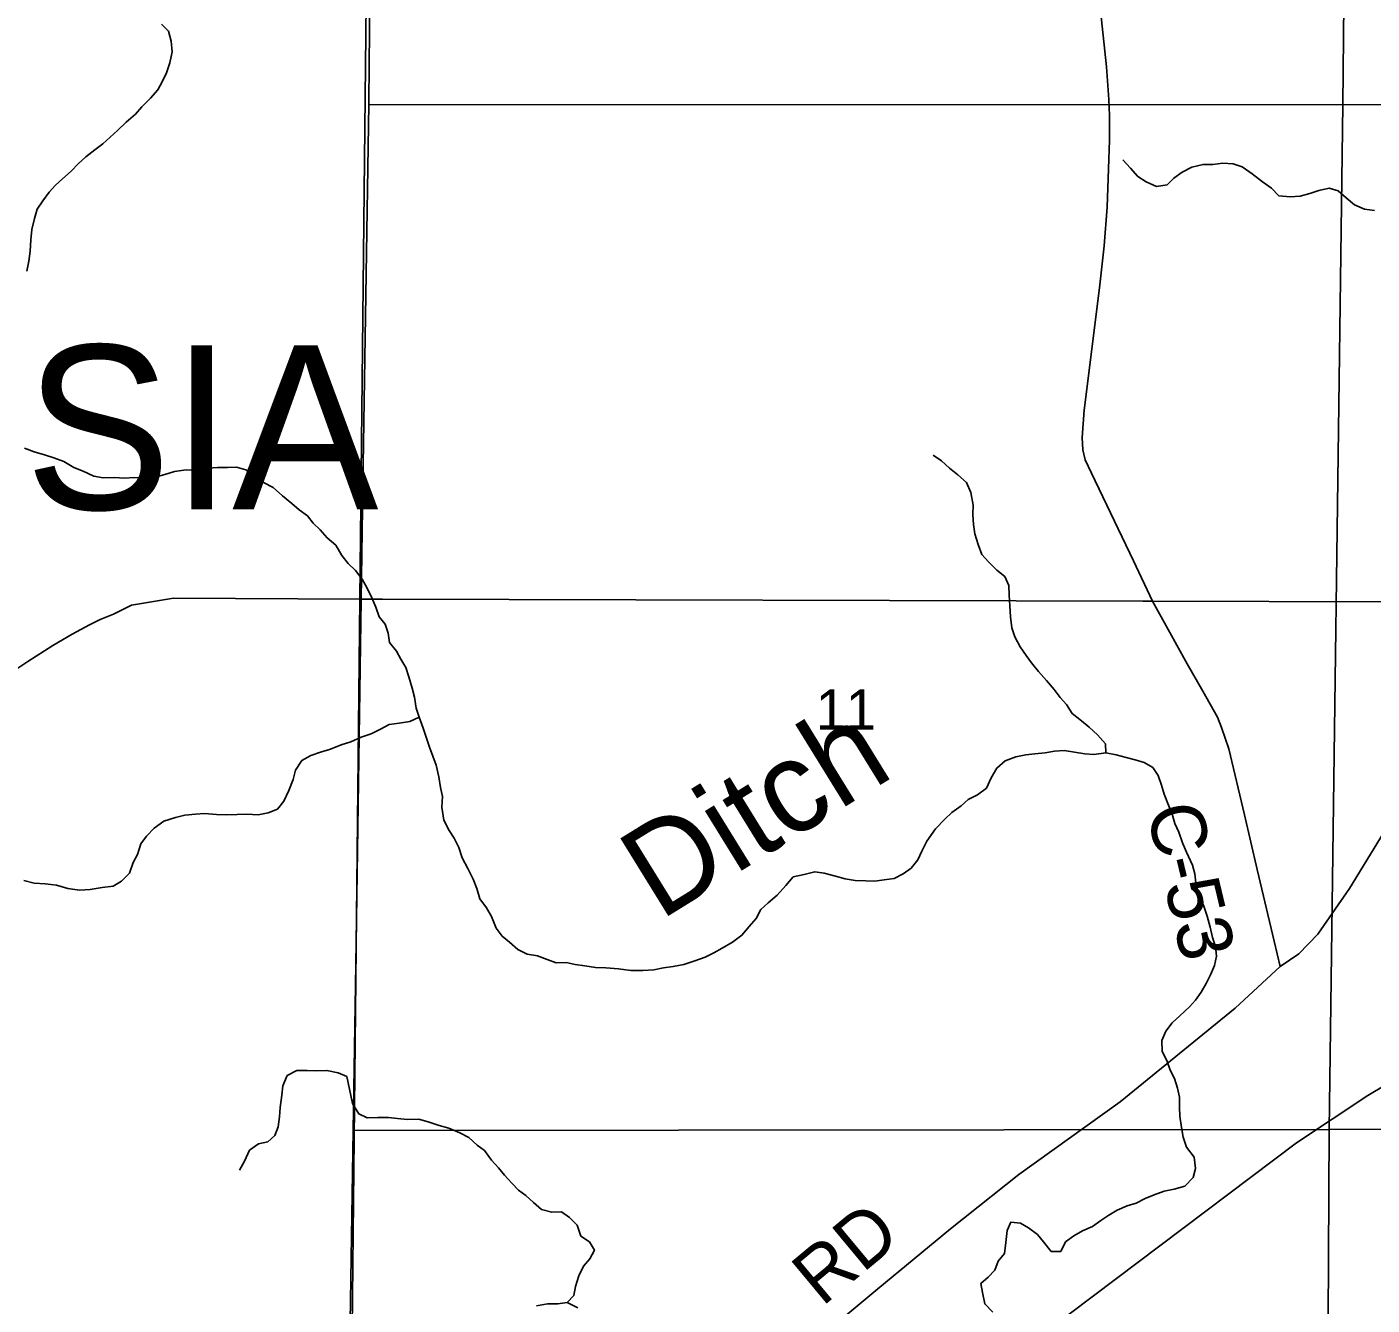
# Model space of a CAD drawing. Extents: x 1857828 to 2277390, y 930619 to 1324581.
# Drawn here: x 2058380 to 2065754, y 1203389 to 1210395 of the extents above; entities that cross this region are included whole.
import ezdxf

# ---------------------------------------------------------------- set-up
doc = ezdxf.new("R2010")
doc.units = 0
for name, color, linetype in [('GM_X_County_Road', 7, 'Continuous'), ('GM_X_County_Road_Text', 7, 'Continuous'), ('GM_X_Minor_River', 7, 'Continuous'), ('GM_X_Minor_River_Text', 7, 'Continuous'), ('GM_X_Section', 7, 'Continuous'), ('GM_X_Section_Text', 7, 'Continuous'), ('GM_X_Township', 7, 'Continuous'), ('GM_X_Township_Road', 7, 'Continuous'), ('GM_X_Township_Text', 7, 'Continuous'), ('GM_X_US_Route', 7, 'Continuous')]:
    doc.layers.add(name, color=color, linetype=linetype)

msp = doc.modelspace()

# ---------------------------------------------------------------- linework, layer by layer
at = {"layer": 'GM_X_County_Road'}
for points in [[(2064549.9, 1207247.2), (2064446.4, 1207468.3), (2064216.2, 1207950), (2064181.6, 1208021.9), (2064167.5, 1208077.3), (2064163.8, 1208144.2), (2064175.6, 1208295), (2064259.9, 1208964.2), (2064285.9, 1209194.8), (2064301.5, 1209407.9), (2064309.7, 1209616.9), (2064314.4, 1209774), (2064314.6, 1209909.9), (2064310.8, 1209997.3), (2064297.5, 1210177.2), (2064265.8, 1210485)], [(2060140.1, 1201171.9), (2060205.6, 1201229.4), (2061510.6, 1202210.1), (2062685.1, 1203178.1), (2063045, 1203479.1), (2063443.3, 1203807.8), (2063817.2, 1204104.5), (2064372.5, 1204503.7), (2065003.2, 1205016.3), (2065250.1, 1205245.6), (2065353, 1205315.3), (2065456.4, 1205422.5), (2065629.4, 1205673.4), (2066300.4, 1206769.3), (2066531.4, 1207209.6)], [(2065250.1, 1205245.6), (2065217.4, 1205384), (2065124.4, 1205777.5), (2065054, 1206075.6), (2064968.1, 1206439.1), (2064929.4, 1206555.6), (2064907.5, 1206612.1), (2064826.3, 1206754.6), (2064741.2, 1206904), (2064549.9, 1207247.2)]]:
    msp.add_lwpolyline(points, dxfattribs=at)
at = {"layer": 'GM_X_Minor_River'}
for points in [[(2058378.6, 1209057.1), (2058390.8, 1209111.1), (2058397, 1209165.2), (2058401.3, 1209227.3), (2058407.5, 1209285.4), (2058421.8, 1209345.5), (2058436, 1209395.6), (2058466.2, 1209441.5), (2058502.4, 1209489.5), (2058536.6, 1209527.4), (2058574.7, 1209563.3), (2058622.9, 1209605.2), (2058661.1, 1209645.1), (2058703.2, 1209683), (2058751.4, 1209720.8), (2058795.5, 1209754.7), (2058835.7, 1209790.6), (2058875.8, 1209826.5), (2058924, 1209872.4), (2058974.2, 1209916.3), (2059010.4, 1209956.2), (2059056.6, 1210004.1), (2059096.8, 1210050), (2059123, 1210098), (2059145.2, 1210144), (2059163.4, 1210198), (2059175.6, 1210258.1), (2059169.9, 1210316.3), (2059156.1, 1210372.4), (2059118.3, 1210410.7)], [(2065766.6, 1209388.5), (2065712.6, 1209396.5), (2065658.5, 1209420.5), (2065612.4, 1209458.5), (2065568.3, 1209496.5), (2065518.3, 1209510.5), (2065462.3, 1209498.4), (2065412.3, 1209482.3), (2065360.3, 1209468.1), (2065304.3, 1209464.1), (2065242.3, 1209470), (2065202.2, 1209512), (2065154.1, 1209546), (2065096, 1209590.1), (2065041.9, 1209628.1), (2064991.9, 1209644), (2064935.9, 1209648), (2064881.9, 1209641.9), (2064827.9, 1209641.8), (2064765.9, 1209625.7), (2064712, 1209599.6), (2064668, 1209565.4), (2064630.1, 1209529.3), (2064572.1, 1209521.2), (2064516.1, 1209545.2), (2064470, 1209575.2), (2064429.9, 1209621.2), (2064387.7, 1209667.2)], [(2060026, 1207594.5), (2059987.9, 1207638.6), (2059949.8, 1207674.6), (2059917.7, 1207714.6), (2059871.6, 1207748.7), (2059831.5, 1207782.7), (2059781.4, 1207824.7), (2059729.3, 1207870.7), (2059677.2, 1207898.7), (2059629.2, 1207936.8), (2059579.1, 1207966.7), (2059529, 1207982.7), (2059479, 1207980.6), (2059425, 1207980.6), (2059373, 1207976.5), (2059319, 1207966.4), (2059253, 1207968.3), (2059189, 1207958.2), (2059135.1, 1207942.1), (2059075.1, 1207925.9), (2059017.1, 1207923.9), (2058967.1, 1207925.8), (2058915.1, 1207921.7), (2058859.1, 1207925.6), (2058797.1, 1207923.6), (2058747.1, 1207933.5), (2058689, 1207959.5), (2058636.9, 1207979.5), (2058582.8, 1208013.4), (2058526.8, 1208033.4), (2058476.7, 1208049.4), (2058418.7, 1208065.3), (2058366.7, 1208085.3)], [(2064295.3, 1206415.9), (2064291.8, 1206465.9), (2064248, 1206514.2), (2064202.2, 1206556.5), (2064160.3, 1206590.8), (2064110.5, 1206631.1), (2064078.7, 1206681.3), (2064044.9, 1206719.6), (2064011.1, 1206763.8), (2063969.3, 1206812.1), (2063925.5, 1206862.4), (2063887.7, 1206908.7), (2063857.8, 1206949), (2063824, 1206997.2), (2063796.3, 1207051.5), (2063778.5, 1207101.7), (2063772.7, 1207161.8), (2063769, 1207222), (2063765.2, 1207280.1), (2063763.4, 1207334.2), (2063741.6, 1207382.5), (2063697.8, 1207416.7), (2063652, 1207463.1), (2063614.2, 1207503.3), (2063594.4, 1207557.5), (2063576.6, 1207615.8), (2063568.8, 1207667.9), (2063565.1, 1207722), (2063567.3, 1207774.1), (2063553.6, 1207842.3), (2063529.8, 1207898.6), (2063484, 1207940.9), (2063438.1, 1207977.2), (2063394.3, 1208017.5), (2063348.4, 1208047.8)], [(2063855.2, 1206405.2), (2063801.2, 1206395.1), (2063743.3, 1206373), (2063697.4, 1206332.8), (2063665.5, 1206278.7), (2063639.6, 1206222.5), (2063591.7, 1206186.4), (2063539.8, 1206160.2), (2063501.8, 1206126.1), (2063449.9, 1206089.9), (2063412, 1206051.8), (2063360.1, 1205999.6), (2063312.3, 1205931.4), (2063286.4, 1205877.2), (2063264.5, 1205829.1), (2063226.6, 1205785), (2063182.7, 1205752.8), (2063134.7, 1205726.7), (2063078.7, 1205720.6), (2063028.7, 1205712.5), (2062978.7, 1205714.4), (2062920.7, 1205716.4), (2062864.7, 1205726.3), (2062812.6, 1205740.3), (2062750.6, 1205756.2), (2062698.6, 1205764.2), (2062640.6, 1205750.1), (2062580.6, 1205735.9), (2062540.7, 1205689.8), (2062492.8, 1205635.6), (2062442.9, 1205593.4), (2062403, 1205557.3), (2062377.1, 1205509.1), (2062339.2, 1205465), (2062299.3, 1205416.8), (2062247.4, 1205378.7), (2062191.5, 1205346.5), (2062145.5, 1205320.4), (2062097.6, 1205296.3), (2062041.6, 1205276.1), (2061981.7, 1205256), (2061921.7, 1205245.9), (2061869.7, 1205237.8), (2061815.7, 1205227.7), (2061755.7, 1205223.6), (2061689.7, 1205223.5), (2061623.7, 1205231.5), (2061553.6, 1205237.4), (2061497.6, 1205239.3), (2061437.6, 1205249.2), (2061385.6, 1205255.2), (2061335.6, 1205267.1), (2061281.5, 1205265.1), (2061231.5, 1205283), (2061179.5, 1205303), (2061121.4, 1205312.9), (2061071.4, 1205338.9), (2061025.3, 1205378.9), (2060985.2, 1205411), (2060953.1, 1205455), (2060926.9, 1205519.1), (2060898.8, 1205567.2), (2060862.7, 1205615.2), (2060846.6, 1205673.3), (2060826.4, 1205723.4), (2060796.3, 1205781.5), (2060766.2, 1205841.6), (2060748, 1205897.7), (2060721.9, 1205947.8), (2060693.8, 1205989.8), (2060665.7, 1206047.9), (2060653.5, 1206118.1), (2060657.4, 1206176.2), (2060647.2, 1206226.3), (2060637.1, 1206284.4), (2060623, 1206348.6), (2060604.8, 1206398.6), (2060586.7, 1206446.7), (2060570.6, 1206496.8), (2060552.5, 1206550.9), (2060530.3, 1206611), (2060514.2, 1206661.1), (2060504.1, 1206721.2), (2060492, 1206771.3), (2060473.8, 1206833.4), (2060457.7, 1206883.5), (2060429.6, 1206929.6), (2060405.5, 1206973.7), (2060367.4, 1207021.7), (2060359.3, 1207071.8), (2060343.1, 1207121.9), (2060311, 1207161.9), (2060292.9, 1207214.1), (2060270.8, 1207266.1), (2060244.7, 1207318.2), (2060218.5, 1207368.3), (2060180.4, 1207416.3), (2060140.3, 1207454.4), (2060106.2, 1207498.4), (2060074.1, 1207554.5), (2060026, 1207594.5)], [(2060530.3, 1206611), (2060478.4, 1206588.9), (2060420.4, 1206578.8), (2060366.4, 1206570.7), (2060318.5, 1206546.6), (2060266.5, 1206520.4), (2060212.6, 1206502.3), (2060154.6, 1206476.2), (2060102.6, 1206460.1), (2060044.7, 1206435.9), (2059988.7, 1206419.8), (2059936.8, 1206401.7), (2059886.8, 1206373.6), (2059852.9, 1206321.4), (2059839.1, 1206269.3), (2059815.2, 1206209.1), (2059787.3, 1206150.9), (2059753.4, 1206106.8), (2059701.5, 1206086.7), (2059647.5, 1206076.6), (2059585.5, 1206080.5), (2059531.5, 1206078.4), (2059475.5, 1206076.3), (2059419.4, 1206078.3), (2059353.4, 1206084.2), (2059303.4, 1206080.1), (2059245.4, 1206074), (2059193.5, 1206061.9), (2059129.5, 1206041.8), (2059077.6, 1206003.6), (2059035.7, 1205959.4), (2059003.8, 1205917.3), (2058985.9, 1205859.1), (2058962, 1205815), (2058942.1, 1205756.8), (2058898.2, 1205712.7), (2058852.3, 1205684.6), (2058792.3, 1205678.5), (2058726.3, 1205666.3), (2058668.3, 1205664.3), (2058604.3, 1205672.2), (2058542.2, 1205690.1), (2058480.2, 1205698.1), (2058420.2, 1205702), (2058362.2, 1205715.9)], [(2063674.3, 1203350.1), (2063630.2, 1203396.1), (2063618, 1203458.2), (2063609.9, 1203508.3), (2063649.8, 1203542.5), (2063685.7, 1203580.6), (2063703.6, 1203630.8), (2063739.5, 1203672.9), (2063745.4, 1203733.1), (2063753.2, 1203797.2), (2063773.1, 1203843.3), (2063827.2, 1203837.4), (2063871.2, 1203813.4), (2063919.3, 1203775.4), (2063953.4, 1203735.3), (2063995.5, 1203683.3), (2064047.5, 1203683.4), (2064073.4, 1203735.5), (2064119.4, 1203769.7), (2064167.3, 1203795.8), (2064221.2, 1203819.9), (2064267.2, 1203852.1), (2064311.1, 1203882.2), (2064357.1, 1203910.3), (2064411, 1203932.4), (2064461, 1203948.6), (2064510.9, 1203972.7), (2064558.9, 1203992.8), (2064614.9, 1204012.9), (2064668.8, 1204025), (2064726.8, 1204041.1), (2064772.7, 1204089.3), (2064786.6, 1204137.4), (2064778.5, 1204199.6), (2064736.3, 1204255.6), (2064718.2, 1204309.7), (2064710.1, 1204361.8), (2064699.9, 1204424), (2064697.8, 1204474.1), (2064697.7, 1204528.2), (2064687.6, 1204578.3), (2064671.4, 1204630.4), (2064647.3, 1204676.4), (2064629.2, 1204730.6), (2064603.1, 1204778.6), (2064600.9, 1204838.8), (2064622.8, 1204890.9), (2064658.7, 1204937.1), (2064700.6, 1204975.2), (2064752.5, 1205023.4), (2064786.5, 1205061.5), (2064816.4, 1205103.7), (2064844.3, 1205151.8), (2064868.1, 1205199.9), (2064890, 1205250.1), (2064901.9, 1205302.2), (2064895.8, 1205354.3), (2064879.7, 1205404.4), (2064865.5, 1205460.5), (2064849.4, 1205520.6), (2064831.3, 1205576.7), (2064807.1, 1205632.8), (2064789, 1205686.9), (2064782.9, 1205753.1), (2064768.8, 1205801.2), (2064736.6, 1205871.3), (2064714.5, 1205923.3), (2064694.3, 1205981.4), (2064672.2, 1206029.5), (2064658.1, 1206079.6), (2064638, 1206129.7), (2064613.8, 1206189.8), (2064599.7, 1206239.9), (2064581.6, 1206292), (2064551.5, 1206336.1), (2064505.4, 1206364), (2064455.4, 1206378), (2064405.3, 1206390), (2064351.3, 1206405.9), (2064295.3, 1206415.9), (2064229.3, 1206407.8), (2064179.3, 1206411.7), (2064123.2, 1206419.6), (2064065.2, 1206429.6), (2064013.2, 1206425.5), (2063961.2, 1206415.4), (2063905.2, 1206411.3), (2063855.2, 1206405.2)], [(2061341.9, 1203402.9), (2061377.8, 1203441), (2061387.7, 1203491.2), (2061405.5, 1203549.3), (2061431.4, 1203603.5), (2061465.3, 1203643.6), (2061491.2, 1203689.8), (2061463.1, 1203735.8), (2061417, 1203767.8), (2061396.9, 1203827.9), (2061354.8, 1203870), (2061310.7, 1203900), (2061256.7, 1203897.9), (2061200.7, 1203913.9), (2061156.6, 1203951.9), (2061114.5, 1203989.9), (2061074.4, 1204019.9), (2061038.3, 1204058), (2060998.2, 1204102), (2060964.1, 1204142.1), (2060926, 1204184.1), (2060887.9, 1204236.2), (2060847.8, 1204266.2), (2060801.7, 1204308.2), (2060753.6, 1204334.2), (2060693.6, 1204358.2), (2060639.5, 1204374.1), (2060585.5, 1204392.1), (2060527.4, 1204408), (2060465.4, 1204405.9), (2060411.4, 1204411.9), (2060361.4, 1204417.8), (2060303.4, 1204417.8), (2060245.4, 1204415.6), (2060199.3, 1204437.6), (2060165.2, 1204493.7), (2060149, 1204571.9), (2060132.9, 1204642), (2060086.8, 1204662), (2060024.8, 1204675.9), (2059968.8, 1204673.8), (2059916.8, 1204675.8), (2059858.8, 1204675.7), (2059806.8, 1204647.6), (2059782.9, 1204591.4), (2059777.1, 1204539.3), (2059767.2, 1204473.1), (2059765.3, 1204421), (2059757.5, 1204366.9), (2059739.6, 1204318.7), (2059699.6, 1204284.6), (2059649.7, 1204272.5), (2059599.7, 1204238.3), (2059571.9, 1204178.2), (2059546, 1204128)], [(2061173.9, 1203384.6), (2061233.9, 1203396.7), (2061289.9, 1203396.8), (2061341.9, 1203402.9), (2061399.9, 1203374.9)]]:
    msp.add_lwpolyline(points, dxfattribs=at)
at = {"layer": 'GM_X_Section'}
for points in [[(2060284.5, 1215697.5), (2065650.4, 1215720.9), (2065593.7, 1209968.9), (2060254.8, 1209970.6), (2060255, 1209988.2), (2060258.8, 1210570.4), (2060274.5, 1213273.4)], [(2065650.4, 1215720.9), (2070962.6, 1215728.7), (2070874.1, 1209998.9), (2065593.7, 1209968.9)], [(2060254.8, 1209970.6), (2065593.7, 1209968.9), (2065519.4, 1204352.4), (2060167.5, 1204346.6), (2060182.6, 1205256.1), (2060220.6, 1207879.8)], [(2065593.7, 1209968.9), (2070874.1, 1209998.9), (2070799.7, 1204378.1), (2065519.4, 1204352.4)], [(2065519.4, 1204352.4), (2065488.8, 1198768.7), (2060096.2, 1198747.6), (2060108.8, 1199925.5), (2060140.8, 1202599.5), (2060167.5, 1204346.6)], [(2070799.7, 1204378.1), (2070731.6, 1198809.7), (2065488.8, 1198768.7), (2065519.4, 1204352.4)]]:
    msp.add_lwpolyline(points, close=True, dxfattribs=at)
at = {"layer": 'GM_X_Township'}
for points in [[(2060293.5, 1215682.6), (2060204.5, 1207259), (2060140.1, 1201171.9), (2060131.4, 1200354.3), (2060127.4, 1199971.2), (2060075, 1195021.5), (2060042.5, 1193100.2), (2056703.2, 1193080.4), (2052995.6, 1193078.3), (2052904.5, 1193058.9), (2046210.9, 1193045.7), (2035008.9, 1192996), (2032348.2, 1192998.4), (2032344.7, 1193489.1), (2032473.9, 1199136.9), (2032547.8, 1208286.9), (2032612.5, 1216299.5)], [(2084053.7, 1193260.9), (2078280.8, 1193208.2), (2073191.4, 1193174), (2068682.3, 1193143.7), (2068071, 1193136.7), (2067855.7, 1193135.1), (2062743.6, 1193117.9), (2061609.4, 1193110.5), (2060042.5, 1193100.2), (2060075, 1195021.5), (2060127.4, 1199971.2), (2060131.4, 1200354.3), (2060140.1, 1201171.9), (2060204.5, 1207259), (2060293.5, 1215682.6)]]:
    msp.add_lwpolyline(points, dxfattribs=at)
at = {"layer": 'GM_X_Township_Road'}
for points in [[(2058158.4, 1206767.3), (2058385, 1206917.5), (2058522.1, 1207004.8), (2058627.5, 1207065.8), (2058722.9, 1207118.6), (2058780.7, 1207147.2), (2058854.3, 1207175.8), (2058953.3, 1207226.1), (2059183.3, 1207264.4), (2060204.4, 1207259), (2060328.4, 1207258.7)], [(2060328.4, 1207258.7), (2064496.9, 1207247.3), (2064549.9, 1207247.2)], [(2064549.9, 1207247.2), (2065826.7, 1207244.8), (2066171.3, 1207228), (2066359.2, 1207221.5), (2066483.1, 1207218.6), (2066531.4, 1207209.6)]]:
    msp.add_lwpolyline(points, dxfattribs=at)
at = {"layer": 'GM_X_US_Route'}
msp.add_lwpolyline([(2054677.9, 1195170.3), (2054837.4, 1195352.9), (2055032, 1195549.7), (2055173.6, 1195679.7), (2055317.8, 1195799.7), (2056203.6, 1196482.3), (2056601.3, 1196831.2), (2057041, 1197329.5), (2057849.7, 1198281.9), (2058613.4, 1199064.3), (2059059.7, 1199476.8), (2059264.5, 1199666), (2059500.2, 1199857.9), (2059938.7, 1200214.7), (2060131.4, 1200354.4), (2065339.2, 1204278.5), (2065730.3, 1204538.2), (2066214.7, 1204827.1), (2069304.1, 1206604.3)], dxfattribs=at)

# ---------------------------------------------------------------- texts
at = {"layer": 'GM_X_County_Road_Text'}
for s, rotation, p in [('C-53', 283.45014, (2064515.1, 1206104.3)), ('RD', 39.74081, (2062738.4, 1203376.4))]:
    msp.add_text(s, height=300, rotation=rotation, dxfattribs=at).set_placement(p)
at = {"layer": 'GM_X_Minor_River_Text'}
msp.add_text('Ditch', height=500.25, rotation=31.70245, dxfattribs=at).set_placement((2061849.2, 1205493.1))
at = {"layer": 'GM_X_Section_Text'}
msp.add_text('11', height=221, rotation=0.00001, dxfattribs=at).set_placement((2062705.1, 1206543.1))
at = {"layer": 'GM_X_Township_Text'}
msp.add_text('NEW RUSSIA', height=900, rotation=0.00001, dxfattribs=at).set_placement((2052684.5, 1207750.5))

doc.saveas('drawing.dxf')
